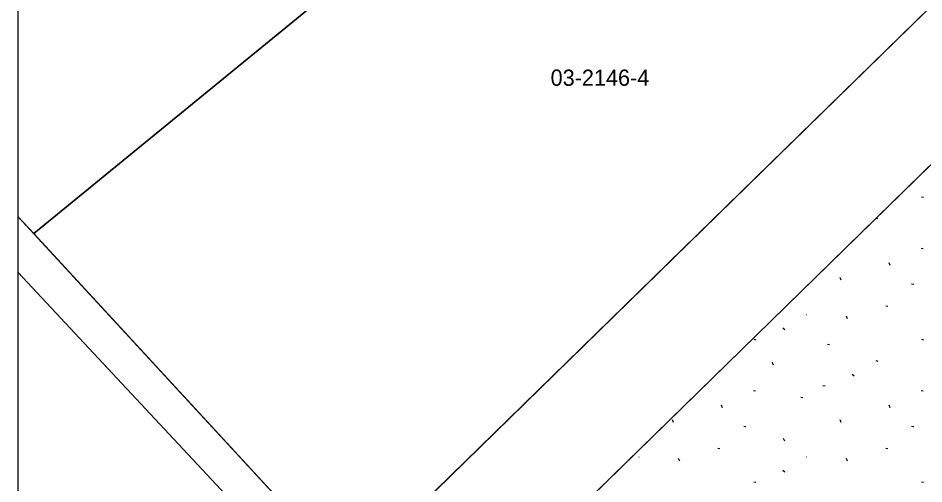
# Model space of a CAD drawing. Extents: x 413946 to 415528, y 4453939 to 4454944.
# Drawn here: x 413945.6 to 414001.6, y 4454115.8 to 4454144.6 of the extents above; entities that cross this region are included whole.
import ezdxf

# ---------------------------------------------------------------- set-up
doc = ezdxf.new("R2010")
doc.units = 0
for name, color, linetype in [('0_KADASTRO', 7, 'Continuous'), ('0_ÇERÇEVE', 7, 'Continuous'), ('Level 28', 7, 'Continuous'), ('Level 41', 7, 'Continuous'), ('Level 54', 7, 'Continuous'), ('Level 62', 7, 'Continuous')]:
    doc.layers.add(name, color=color, linetype=linetype)

msp = doc.modelspace()

# ---------------------------------------------------------------- linework, layer by layer
at = {"layer": '0_KADASTRO'}
for points in [[(413946.53, 4454131.27), (413964.46, 4454145.95), (413981.71, 4454160.06), (414007.92, 4454181.51), (414023.48, 4454166.35), (413966.01, 4454110.14)], [(413970.76, 4454105), (414009.76, 4454143.15), (414049.49, 4454101.04), (414024.79, 4454071.92), (414002.18, 4454071.38)]]:
    msp.add_lwpolyline(points, close=True, dxfattribs=at)
for points in [[(413945.566, 4454168.919), (413964.46, 4454145.95), (413946.53, 4454131.27), (413945.566, 4454132.315)], [(413945.566, 4454132.315), (413945.566, 4454168.919)]]:
    msp.add_lwpolyline(points, dxfattribs=at)
at = {"layer": '0_ÇERÇEVE'}
msp.add_lwpolyline([(413945.566, 4454943.957), (415494.137, 4454943.957), (415494.137, 4453939.478), (413945.566, 4453939.478)], close=True, dxfattribs=at)
at = {"layer": 'Level 28'}
for p, q in [((414023.48, 4454166.35), (413966.01, 4454110.14)), ((413970.76, 4454105), (414009.76, 4454143.15)), ((413966.01, 4454110.14), (413945.566, 4454132.311))]:
    msp.add_line(p, q, dxfattribs=at)
at = {"layer": 'Level 41'}
for p, q in [((414001.405, 4454133.54), (414001.532, 4454133.515)), ((414001.405, 4454133.54), (414001.532, 4454133.515)), ((413998.587, 4454132.221), (413998.71, 4454132.197)), ((413998.587, 4454132.221), (413998.71, 4454132.197)), ((414001.378, 4454130.374), (414001.505, 4454130.351)), ((414001.378, 4454130.374), (414001.505, 4454130.351)), ((413999.475, 4454129.305), (413999.409, 4454129.467)), ((413999.475, 4454129.305), (413999.409, 4454129.467)), ((413996.444, 4454128.39), (413996.379, 4454128.554)), ((413996.444, 4454128.39), (413996.379, 4454128.554)), ((414000.794, 4454128.17), (414000.92, 4454128.146)), ((414000.794, 4454128.17), (414000.92, 4454128.146)), ((413999.19, 4454126.802), (413999.316, 4454126.778)), ((413999.19, 4454126.802), (413999.316, 4454126.778)), ((413994.306, 4454126.277), (413994.315, 4454126.276)), ((413994.306, 4454126.277), (413994.315, 4454126.276)), ((413996.826, 4454126.008), (413996.761, 4454126.17)), ((413996.826, 4454126.008), (413996.761, 4454126.17)), ((413992.831, 4454125.439), (413992.958, 4454125.34)), ((413992.831, 4454125.439), (413992.958, 4454125.34)), ((413991.037, 4454124.734), (413991.164, 4454124.709)), ((413991.037, 4454124.734), (413991.164, 4454124.709)), ((414001.405, 4454124.734), (414001.532, 4454124.709)), ((414001.405, 4454124.734), (414001.532, 4454124.709)), ((413995.585, 4454124.44), (413995.712, 4454124.416)), ((413995.585, 4454124.44), (413995.712, 4454124.416)), ((413998.585, 4454123.415), (413998.71, 4454123.391)), ((413998.585, 4454123.415), (413998.71, 4454123.391)), ((413992.251, 4454123.136), (413992.186, 4454123.298)), ((413992.251, 4454123.136), (413992.186, 4454123.298)), ((413997.11, 4454122.578), (413997.237, 4454122.478)), ((413997.11, 4454122.578), (413997.237, 4454122.478)), ((413995.315, 4454121.872), (413995.442, 4454121.849)), ((413995.315, 4454121.872), (413995.442, 4454121.849)), ((413991.01, 4454121.568), (413991.137, 4454121.545)), ((413991.01, 4454121.568), (413991.137, 4454121.545)), ((413993.939, 4454121.158), (413994.066, 4454121.134)), ((413993.939, 4454121.158), (413994.066, 4454121.134)), ((414001.378, 4454121.568), (414001.505, 4454121.545)), ((414001.378, 4454121.568), (414001.505, 4454121.545)), ((413989.107, 4454120.499), (413989.041, 4454120.661)), ((413989.107, 4454120.499), (413989.041, 4454120.661)), ((413999.475, 4454120.499), (413999.409, 4454120.661)), ((413999.475, 4454120.499), (413999.409, 4454120.661)), ((413986.076, 4454119.584), (413986.011, 4454119.748)), ((413986.076, 4454119.584), (413986.011, 4454119.748)), ((413996.444, 4454119.584), (413996.379, 4454119.748)), ((413996.444, 4454119.584), (413996.379, 4454119.748)), ((413990.426, 4454119.364), (413990.552, 4454119.34)), ((413990.426, 4454119.364), (413990.552, 4454119.34)), ((414000.794, 4454119.364), (414000.92, 4454119.34)), ((414000.794, 4454119.364), (414000.92, 4454119.34)), ((413992.948, 4454118.435), (413992.884, 4454118.596)), ((413992.948, 4454118.435), (413992.884, 4454118.596)), ((413988.822, 4454117.996), (413988.948, 4454117.972)), ((413988.822, 4454117.996), (413988.948, 4454117.972)), ((413999.19, 4454117.996), (413999.316, 4454117.972)), ((413999.19, 4454117.996), (413999.316, 4454117.972)), ((413983.938, 4454117.471), (413983.947, 4454117.47)), ((413983.938, 4454117.471), (413983.947, 4454117.47)), ((413986.458, 4454117.202), (413986.393, 4454117.364)), ((413986.458, 4454117.202), (413986.393, 4454117.364)), ((413994.306, 4454117.471), (413994.315, 4454117.47)), ((413994.306, 4454117.471), (413994.315, 4454117.47)), ((413996.826, 4454117.202), (413996.761, 4454117.364)), ((413996.826, 4454117.202), (413996.761, 4454117.364)), ((413992.831, 4454116.633), (413992.958, 4454116.534)), ((413992.831, 4454116.633), (413992.958, 4454116.534)), ((413982.568, 4454116.551), (413982.59, 4454116.534)), ((413982.568, 4454116.551), (413982.59, 4454116.534)), ((413991.037, 4454115.928), (413991.164, 4454115.903)), ((413991.037, 4454115.928), (413991.164, 4454115.903)), ((414001.405, 4454115.928), (414001.532, 4454115.903)), ((414001.405, 4454115.928), (414001.532, 4454115.903))]:
    msp.add_line(p, q, dxfattribs=at)
at = {"layer": 'Level 54'}
for points in [[(413945.566, 4454169.9), (413962.52, 4454183.5), (413986.09, 4454202.4), (414007.92, 4454181.51), (414023.48, 4454166.35), (413966.01, 4454110.14), (413945.566, 4454132.311)], [(413945.566, 4454132.311), (413945.566, 4454169.9)]]:
    msp.add_lwpolyline(points, dxfattribs=at)
at = {"layer": 'Level 62'}
msp.add_line((413973.028, 4454099.454), (413945.566, 4454128.867), dxfattribs=at)

# ---------------------------------------------------------------- texts
at = {"layer": '0_KADASTRO'}
msp.add_text('03-2146-4', height=1, dxfattribs=at).set_placement((413978.479, 4454140.414))

doc.saveas('drawing.dxf')
